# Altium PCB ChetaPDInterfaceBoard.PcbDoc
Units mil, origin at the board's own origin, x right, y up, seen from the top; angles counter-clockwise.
Board outline 6400 x 2000 mil, 2 copper layers (Top Layer, Bottom Layer); 32 components, 24 nets, 95 pads, 24 vias.
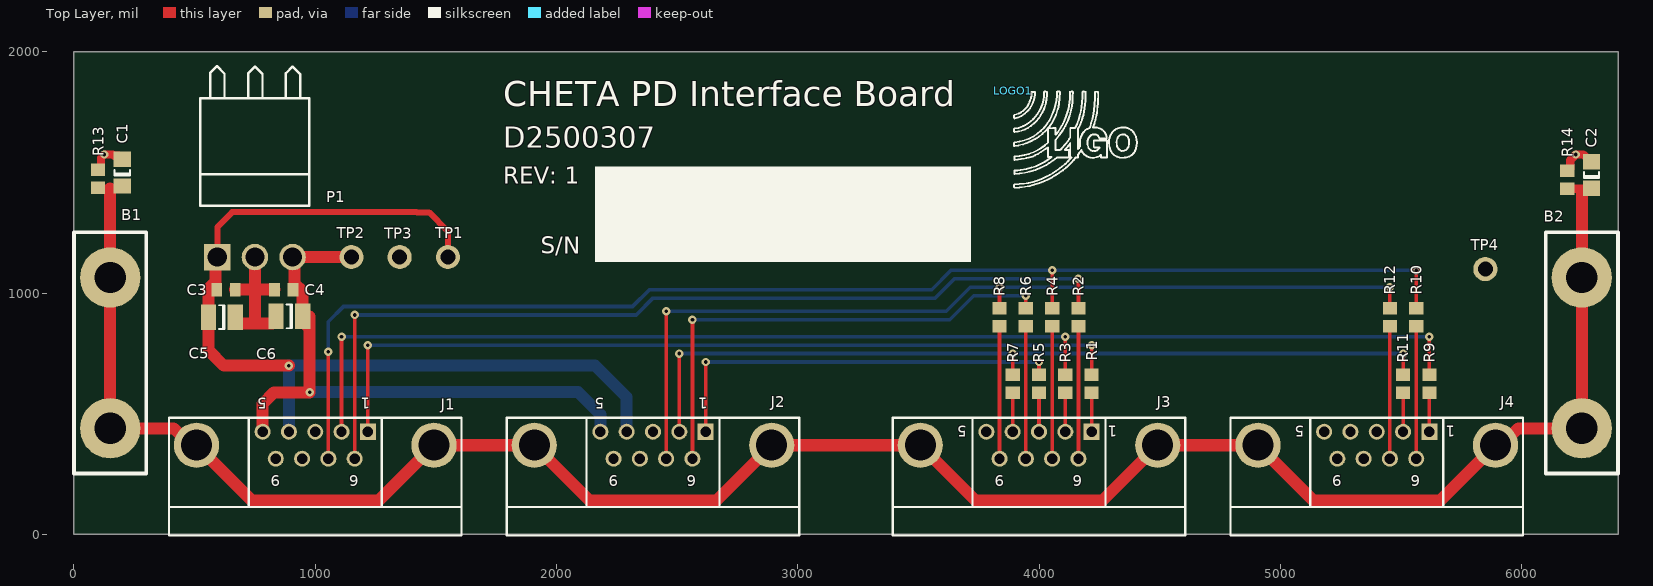
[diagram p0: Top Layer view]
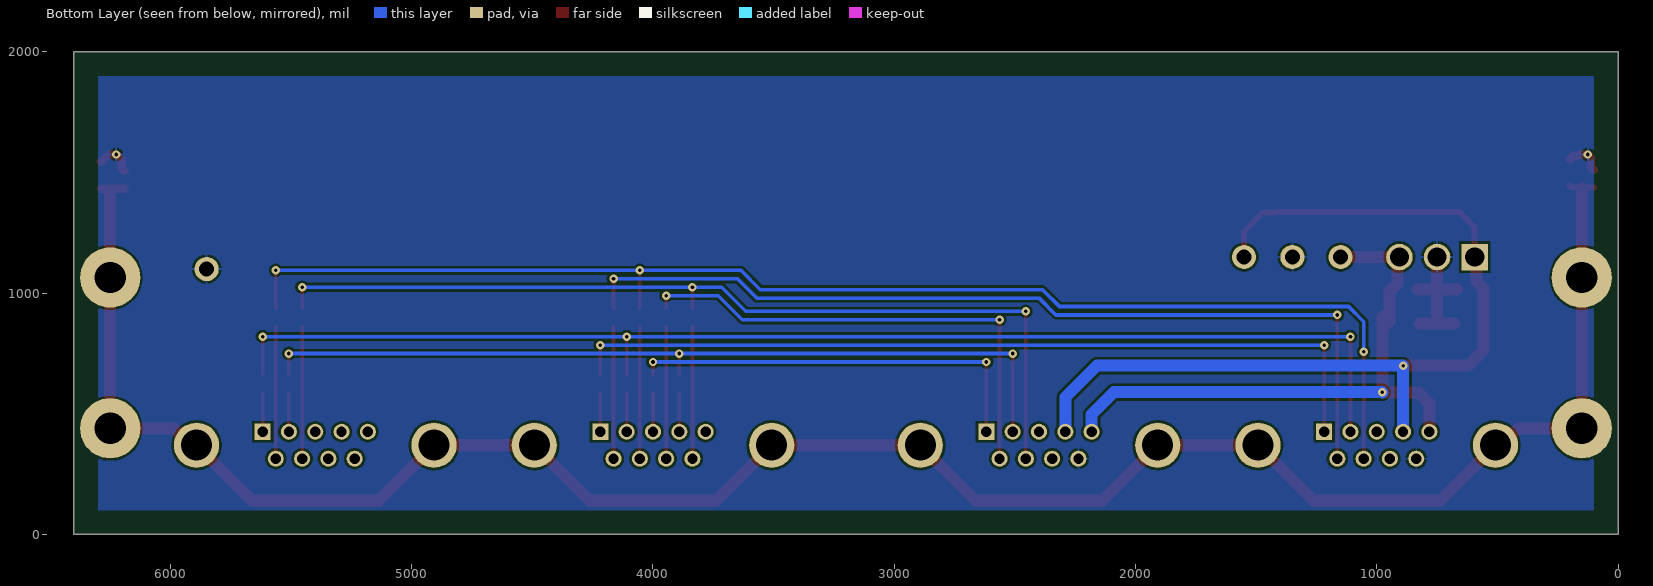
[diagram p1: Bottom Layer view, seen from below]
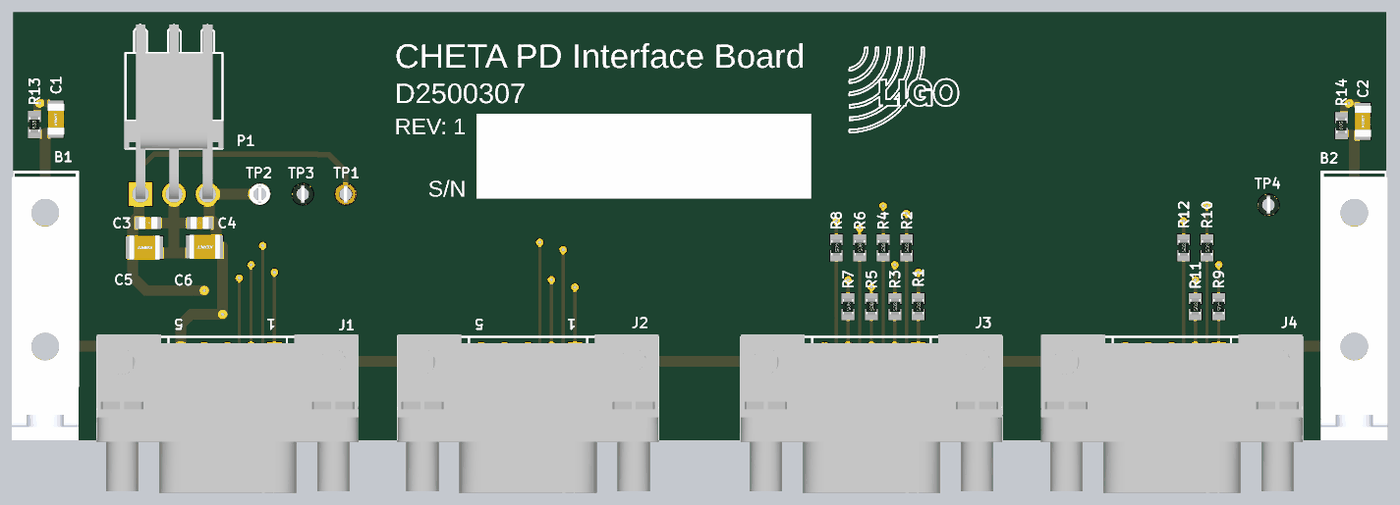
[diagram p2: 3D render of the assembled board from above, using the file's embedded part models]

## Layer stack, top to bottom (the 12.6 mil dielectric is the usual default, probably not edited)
Top Solder: solder mask 0.4, Solder Resist, Dk 3.5
Top Layer: signal copper 1.4
Dielectric 1: dielectric 12.6, FR-4, Dk 4.8
Bottom Layer: signal copper 1.4
Bottom Solder: solder mask 0.4, Solder Resist, Dk 3.5

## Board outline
0,0 0,2000 6400,2000 6400,0

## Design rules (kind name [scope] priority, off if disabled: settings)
Clearance [All] p1: gap=10 ignorepadtopadclearanceinfootprint=FALSE
HoleSize [All] p1: absolutevalues=TRUE maxlimit=200 minlimit=10 maxpercent=80.000 minpercent=20.000
MinimumAnnularRing [All] p1: minimumring=10
MinimumSolderMaskSliver [All] p1: minsoldermaskwidth=1
PolygonConnect [All] p1: connectstyle=Relief reliefconductorwidth=10 reliefentries=4 polygonreliefangle="90 Angle" airgapwidth=10
RoutingVias [All] p1: holewidth=15 width=35 viastyle="Through Hole" minholewidth=10 minwidth=25 maxholewidth=35 maxwidth=50
SilkToSolderMaskClearance [IsPad] p1: minsilkscreentomaskgap=7 clearancetoexposedcopper=TRUE
SolderMaskExpansion [All] p1: expansion=4 istentingtop=FALSE
SupplyNets "Schematic Supply Nets_2" [InNet('GND')] p1: voltage=0.000
SupplyNets "Schematic Supply Nets_1" [InNet('+15')] p2: voltage=0.000
SupplyNets "Schematic Supply Nets" [InNet('-15')] p3: voltage=0.000
Width [All] p1: maxlimit=100 minlimit=10 preferedwidth=15
27 further rules are at their usual default settings.

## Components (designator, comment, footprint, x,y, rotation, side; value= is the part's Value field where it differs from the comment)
B1 "Bracket" Bracket-RA_708 150,440 r0 top locked
B2 "Bracket" Bracket-RA_708 6250,440 r0 top locked
C1 "NL" CC3216-1206 200,1500 r90 top
C2 "NL" CC3216-1206 6290,1490 r90 top
C3 "100n" CC2013-0805 630,1015 r180 top
C4 "100n" CC2013-0805 870,1015 r180 top
C5 "10u" CC3225-1210 613,901 r180 top
C6 "10u" CC3225-1210 893,904 r180 top
J1 "DB9F" DB9F-RA 1000,370 r180 top locked
J2 "DB9F" DB9F-RA 2400,370 r180 top locked
J3 "DB9F" DB9F-RA 4000,370 r180 top locked
J4 "DB9F" DB9F-RA 5400,370 r180 top locked
LOGO1 "LIGO logo" LIGO_LOGO 3894,1839 r0 top
P1 "Header 3H" Molex_156_RA_3 594,1150 r90 top
R1 "10" CR2012-0805 4218.11,625 r270 top locked
R2 "10" CR2012-0805 4163.58,900 r270 top locked
R3 "10" CR2012-0805 4109.06,625 r270 top locked
R4 "10" CR2012-0805 4054.53,900 r270 top locked
R5 "10" CR2012-0805 4000,625 r270 top locked
R6 "10" CR2012-0805 3945.47,900 r270 top locked
R7 "10" CR2012-0805 3890.94,625 r270 top locked
R8 "10" CR2012-0805 3836.42,900 r270 top locked
R9 "10" CR2012-0805 5618.11,625 r270 top locked
R10 "10" CR2012-0805 5563.58,900 r270 top locked
R11 "10" CR2012-0805 5509.06,625 r270 top locked
R12 "10" CR2012-0805 5454.53,900 r270 top locked
R13 "NL" CR2012-0805 100,1475 r90 top
R14 "NL" CR2012-0805 6190,1470 r90 top
TP1 "+15" TP1-RED 1550,1150 r0 top
TP2 "-15" TP1-WHT 1150,1150 r0 top
TP3 "GND" TP1-BLK 1350,1150 r0 top
TP4 "GND" TP1-BLK 5850,1100 r0 top

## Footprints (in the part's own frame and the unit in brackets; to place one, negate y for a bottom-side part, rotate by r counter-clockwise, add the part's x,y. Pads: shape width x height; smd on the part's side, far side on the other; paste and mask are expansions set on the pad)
Bracket-RA_708 [mil] "Keystone Electronics right-angle 6-32 steel, 708"
  round 250 hole 130: 1(0,0) 2(0,625)
  silkscreen extent -150,-187 150,813, body extent -156,-439 156,791, height 390
CC2013-0805 [mm] "Chip Capacitor; Body 2.0 x 1.3 mm (LxW typ)"
  rect 1.15x1.4 smd: 1(-0.975,0) 2(0.975,0)
  body extent -1.1,-0.72 1.1,0.73, height 0.88
CC3216-1206 [mm] "Chip Capacitor; Body 3.2 x 1.6 mm (LxW typ)"
  rect 1.6x1.8 smd: 1(-1.4,0) 2(1.4,0)
  silkscreen extent -0.3,-0.8 0.3,0.8, body extent -1.85,-0.97 1.85,0.97, height 0.88
CC3225-1210 [mm] "Chip Capacitor; Body 3.2 x 2.5 mm (LxW typ)"
  rect 1.6x2.7 smd: 1(-1.4,0) 2(1.4,0)
  silkscreen extent -0.3,-1.25 0.3,1.25, body extent -1.85,-1.45 1.85,1.45, height 1.4
CR2012-0805 [mm] "Chip Resistor; Body 2.0 x 1.3 mm (LxW typ)"
  rect 1.3x1.5 smd: 1(-0.95,0) 2(0.95,0)
  body extent -1,-0.62 1,0.63, height 0.46
DB9F-RA [mm] "Receptiacle; D Subminiature 9 Position; Right Angle"
  rect 1.69x1.69 hole 1.09: 1(-5.54,-1.42)
  round 1.69 hole 1.09: 2(-2.77,-1.42) 3(0,-1.42) 4(2.77,-1.42) 5(5.54,-1.42) 6(-4.155,1.42) 7(-1.385,1.42) 8(1.385,1.42) 9(4.155,1.42)
  round 4.76 hole 3.26: 10(-12.495,0) 11(12.495,0)
  silkscreen extent -15.4,-2.9 15.4,9.5, body extent -15.49,-3.17 15.49,15.72, height 12.62
LIGO_LOGO [mil] "LIGO logo"
  silkscreen extent 3,-402 511,-3
Molex_156_RA_3 [mil]
  rect 110x110 hole 80: 1(0,0)
  round 110 hole 80: 2(0,-156) 3(0,-312)
  silkscreen extent 213,-382 792,70, body extent -24,-386 792,76, height 394
TP1-BLK [mm] "Testpoint pin, black"
  round 2.54 hole 1.58: 1(0,0)
  body extent -1.27,-1.27 1.27,1.27, height 4.89
TP1-RED [mm] "Testpoint pin, red"
  round 2.54 hole 1.58: 1(0,0)
  body extent -1.27,-1.27 1.27,1.27, height 4.89
TP1-WHT [mm] "Testpoint pin, white"
  round 2.54 hole 1.58: 1(0,0)
  body extent -1.27,-1.27 1.27,1.27, height 4.89

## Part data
B1 B2: library part Bracket_708, "Keystone Electronics right-angle 6-32 steel, 708", Part Number=36-708-ND
C1 C2: library part ChipCap, "Capacitor, surface mount", Tolerance=10%
C3 C4: library part ChipCap, "Capacitor, surface mount", Part Number=311-1140-1-ND, Tolerance=10%
C5 C6: library part ChipCap, "Capacitor, surface mount", Part Number=490-4798-1-ND, Tolerance=10%, Voltage Rating=50V
J1 J2 J3 J4: "Receptacle Assembly, 9 Position, Right Angle, .318 Series", Part Number=A32119-ND
LOGO1: library part LIGO_logo
P1: "Header, 3-Pin, Right Angle", Part Number=WM5236-ND
R1 R2 R3 R4 R5 R6 R7 R8 R9 R10 R11 R12: library part ChipRes1, "Resistor, surface mount", Part Number=RR12Q10DCT-ND, Tolerance=0.5%
R13 R14: library part ChipRes1, "Resistor, surface mount", Tolerance=0.5%
TP1: library part TP_POSITIVE, "Testpoint, red", Part Number=5005K-ND
TP2: library part TP_NEGATIVE, "Testpoint, white", Part Number=5007K-ND
TP3 TP4: library part TP_GND, "Testpoint, black", Part Number=5006K-ND

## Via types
v1: diameter 35, hole 15, Top Layer to Bottom Layer, 24 vias

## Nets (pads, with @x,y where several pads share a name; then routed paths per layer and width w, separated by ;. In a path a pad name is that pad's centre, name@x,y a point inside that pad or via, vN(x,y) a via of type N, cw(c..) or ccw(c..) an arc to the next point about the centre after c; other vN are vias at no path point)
+15: C3.2 C5.2 J1.4 J2.4 P1.1 TP1.1 | length 3877.8
  Top Layer w25: P1.1 594,1274 656,1336 1420,1336 1421,1335 1472,1335 1550,1257 TP1.1
  Top Layer w50: P1.1 587.29,1143.29 587.29,1049.29 558,1020 558,763 621,700 v1(890.94,700)
  Bottom Layer w50: J1.4 v1(890.94,700) 2160,700 2290.94,569.06 J2.4
-15: C4.1 C6.1 J1.5 J2.5 P1.3 TP2.1 | length 2507.9
  Top Layer w50: J1.5 781.89,541.89 829,589 v1(977,589) C6.1@977,903.46 ; P1.3 P1.3@908.39,1150 ; C6.1@948.12,882.35 C6.1@977,853.46 ; C6.1 947,905.12 947,1007 914.12,1039.88 914.12,1144.27 P1.3@908.39,1150 ; TP2.1 P1.3@908.39,1150
  Bottom Layer w50: v1(977,589) 978,590 2090,590 2181.89,498.11 J2.5
B1: B1.1 B1.2 B2.1 B2.2 C1.1 C2.1 J1.10 J1.11 J2.10 J2.11 J3.10 J3.11 J4.10 J4.11 R13.1 R14.1 | length 9095.6
  Top Layer w25: R13.1 146.36,1437.6 ; 150,1433.96 146.36,1437.6 ; C1.1 192.72,1437.6 146.36,1437.6 ; J1.11@483.24,370 J1.11 ; 6238.86,1432.6 6250,1421.46 ; C2.1@6287.72,1432.6 C2.1
  Top Layer w35: R14.1 6238.86,1432.6 C2.1@6287.72,1432.6
  Top Layer w50: 150,1433.96 B1.2 B1.1 413.24,440 J1.11@483.24,370 ; J1.11 738.07,140 1261.93,140 J1.10 J2.11 2138.07,140 2661.93,140 J2.10 J3.11 3738.07,140 4261.93,140 J3.10 J4.11 5138.07,140 5661.93,140 J4.10 ; J4.10@5916.76,370 5986.76,440 B2.1 B2.2 6250,1421.46
GND: C1.2 C2.2 C3.1 C4.2 C5.1 C6.2 J1.9 J2.9 P1.2 R13.2 R14.2 TP3.1 TP4.1 | length 903.8
  Top Layer w35: R13.2 103.94,1512.4 112.03,1520.49 112.03,1562.03 v1(125,1575) 161.56,1575 167.45,1569.11 186,1569.11 C1.2 ; R14.2 6193.94,1507.4 6202.03,1515.49 6202.03,1552.03 v1(6225,1575) 6256.18,1575 6286.06,1545.12 C2.2
  Top Layer w50: C3.1 750,1015 C4.2 ; C5.1@677.36,875 750,875 ; P1.2 750,1030 750,875 ; C6.2@822.64,875 750,875
NetJ3_1: J3.1 R1.2 | length 161.7
  Top Layer w15: J3.1 R1.2
NetJ3_2: J3.2 R3.2 | length 161.7
  Top Layer w15: J3.2 R3.2
NetJ3_3: J3.3 R5.2 | length 161.7
  Top Layer w15: J3.3 R5.2
NetJ3_4: J3.4 R7.2 | length 161.7
  Top Layer w15: J3.4 R7.2
NetJ3_6: J3.6 R2.2 | length 548.5
  Top Layer w15: J3.6 R2.2
NetJ3_7: J3.7 R4.2 | length 548.5
  Top Layer w15: J3.7 R4.2
NetJ3_8: J3.8 R6.2 | length 548.5
  Top Layer w15: J3.8 R6.2
NetJ3_9: J3.9 R8.2 | length 548.5
  Top Layer w15: J3.9 R8.2
NetJ4_1: J4.1 R9.2 | length 161.7
  Top Layer w15: J4.1 R9.2
NetJ4_2: J4.2 R11.2 | length 161.7
  Top Layer w15: J4.2 R11.2
NetJ4_6: J4.6 R10.2 | length 548.5
  Top Layer w15: J4.6 R10.2
NetJ4_7: J4.7 R12.2 | length 548.5
  Top Layer w15: J4.7 R12.2
PD1_AC_N: J1.6 R2.1 | length 3779.7
  Top Layer w15: J1.6 v1(1163.58,910) ; R2.1 v1(4163.58,1060)
  Bottom Layer w15: v1(1163.58,910) 2329.05,910 ; 2330,910 2400,980 3569.5,980 3649.5,1060 v1(4163.58,1060)
PD1_AC_P: J1.1 R1.1 | length 3482.5
  Top Layer w15: J1.1 v1(1218.11,785) ; R1.1 v1(4218.11,785)
  Bottom Layer w15: v1@1217.31,785 v1(4218.11,785)
PD1_DC_N: J1.7 R4.1 R10.1 | length 5481.1
  Top Layer w15: v1(1054,758) 1054,314.62 J1.7 ; R4.1 v1(4054.53,1095) ; R10.1 v1(5563.58,1095)
  Bottom Layer w15: v1(1054,758) 1054,882 1117,945 2315.19,945 2385.19,1015 3555,1015 3635,1095 v1(4054.53,1095) v1(5563.58,1095)
PD1_DC_P: J1.2 R3.1 R9.1 | length 5218.3
  Top Layer w15: J1.2 v1(1109.05,820) ; R3.1 v1(4109.06,820) ; R9.1 v1(5618.11,820)
  Bottom Layer w15: v1(1109.05,820) v1(4109.06,820) v1(5618.11,820)
PD2_AC_N: J2.6 R6.1 | length 2051.8
  Top Layer w15: J2.6 v1(2563.58,890) ; R6.1 v1(3945.47,990)
  Bottom Layer w15: v1(2563.58,890) 3630,890 3730,990 v1(3945.47,990)
PD2_AC_P: J2.1 R5.1 | length 1723.6
  Top Layer w15: J2.1 v1(2618.11,715) ; R5.1 v1(4000,715)
  Bottom Layer w15: v1(2618.11,715) v1(4000,715)
PD2_DC_N: J2.7 R8.1 R12.1 | length 3827.5
  Top Layer w15: J2.7 v1(2454.53,925) ; R8.1 v1(3836.42,1025) ; R12.1 v1(5454.53,1025)
  Bottom Layer w15: v1(2454.53,925) 3615.5,925 3715.5,1025 v1(3836.42,1025) v1(5454.53,1025)
PD2_DC_P: J2.2 R7.1 R11.1 | length 3499.3
  Top Layer w15: J2.2 v1(2509.06,750) ; R7.1 v1(3890.94,750) ; R11.1 v1(5509.06,750)
  Bottom Layer w15: v1(2509.06,750) v1(3890.94,750) v1(5509.06,750)
pads on no net: J1.3 J1.8 J2.3 J2.8 J3.5 J4.3 J4.4 J4.5 J4.8 J4.9

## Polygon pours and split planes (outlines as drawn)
GND on Bottom Layer "GND_L02_P000" (solid, pour order 0): 100,1900 100,100 6300,100 6300,1900

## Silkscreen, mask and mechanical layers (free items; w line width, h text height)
Top Overlay:
  rectangle: 2159,1130 3719,1525
  text "CHETA PD Interface Board" at 1779,1740 h180
  text "D2500307" at 1779,1575 h150
  text "REV: 1" at 1779,1430 h120
  text "S/N" at 1934,1139 h120
Mechanical 1:
  the board outline again, w10
Drill Drawing:
  circle w10: c100.62,2435.83 r33.33
  lines w10: 67.29,2569.17 83.96,2569.17 83.96,2552.5 117.29,2552.5 117.29,2569.17 133.96,2569.17 133.96,2602.5 117.29,2602.5 117.29,2619.17 83.96,2619.17 83.96,2602.5 67.29,2602.5 67.29,2569.17 ; 67.29,2702.5 133.96,2702.5 133.96,2769.17 67.29,2769.17 67.29,2702.5 ; 67.29,2919.17 133.96,2919.17 100.62,2852.5 67.29,2919.17 ; 67.29,3019.17 83.96,3019.17 100.62,3002.5 117.29,3019.17 133.96,3019.17 117.29,3035.83 133.96,3052.5 117.29,3052.5 100.62,3069.17 83.96,3052.5 67.29,3052.5 83.96,3035.83 67.29,3019.17 ; 67.29,3152.5 100.62,3169.17 133.96,3152.5 117.29,3185.83 133.96,3219.17 100.62,3202.5 67.29,3219.17 83.96,3185.83 67.29,3152.5
  lines w15: 7.5,2357.5 10538.58,2357.5 ; 7.5,3257.5 10538.58,3257.5 ; 558.38,2207.5 558.38,3407.5 ; 1098.24,2207.5 1098.24,3407.5 ; 2247.9,2207.5 2247.9,3407.5 ; 2753.78,2207.5 2753.78,3407.5 ; 3487.58,2207.5 3487.58,3407.5 ; 4987.13,2207.5 4987.13,3407.5 ; 5576.98,2207.5 5576.98,3407.5 ; 6322.78,2207.5 6322.78,3407.5 ; 6972.6,2207.5 6972.6,3407.5 ; 7826.37,2207.5 7826.37,3407.5 ; 9159.98,2207.5 9159.98,3407.5 ; 7.5,2207.5 10538.58,2207.5 10538.58,3407.5 7.5,3407.5 7.5,2207.5
  text "Symbol" at 97.5,3302.5 h72
  text "Count" at 603.38,3302.5 h72
  text "Hole Size" at 1143.24,3302.5 h72
  text "Plated" at 2292.9,3302.5 h72
  text "Hole Type" at 2798.78,3302.5 h72
  text "Drill Layer Pair" at 3532.58,3302.5 h72
  text "Via/Pad" at 5032.13,3302.5 h72
  text "Pad Shape" at 5621.98,3302.5 h72
  text "Template" at 6367.78,3302.5 h72
  text "Description" at 7017.6,3302.5 h72
  text "Hole Tolerance (+)" at 7871.37,3302.5 h72
  text "Hole Tolerance (-)" at 9204.98,3302.5 h72
  text "3" at 603.38,3152.5 h60
  text "80.00mil (2.032mm)" at 1143.24,3152.5 h60
  text "PTH" at 2292.9,3152.5 h60
  text "Round" at 2798.78,3152.5 h60
  text "Top Layer - Bottom Layer" at 3532.58,3152.5 h60
  text "Pad" at 5032.13,3152.5 h60
  text "(Mixed)" at 5621.98,3152.5 h60
  text "(Mixed)" at 6367.78,3152.5 h60
  text "4" at 603.38,3002.5 h60
  text "62.21mil (1.580mm)" at 1143.24,3002.5 h60
  text "PTH" at 2292.9,3002.5 h60
  text "Round" at 2798.78,3002.5 h60
  text "Top Layer - Bottom Layer" at 3532.58,3002.5 h60
  text "Pad" at 5032.13,3002.5 h60
  text "Rounded" at 5621.98,3002.5 h60
  text "c254h158" at 6367.78,3002.5 h60
  text "4" at 603.38,2852.5 h60
  text "130.00mil (3.302mm)" at 1143.24,2852.5 h60
  text "PTH" at 2292.9,2852.5 h60
  text "Round" at 2798.78,2852.5 h60
  text "Top Layer - Bottom Layer" at 3532.58,2852.5 h60
  text "Pad" at 5032.13,2852.5 h60
  text "Rounded" at 5621.98,2852.5 h60
  text "c635h330" at 6367.78,2852.5 h60
  text "8" at 603.38,2702.5 h60
  text "128.35mil (3.260mm)" at 1143.24,2702.5 h60
  text "PTH" at 2292.9,2702.5 h60
  text "Round" at 2798.78,2702.5 h60
  text "Top Layer - Bottom Layer" at 3532.58,2702.5 h60
  text "Pad" at 5032.13,2702.5 h60
  text "Rounded" at 5621.98,2702.5 h60
  text "c476h326" at 6367.78,2702.5 h60
  text "24" at 603.38,2552.5 h60
  text "15.00mil (0.381mm)" at 1143.24,2552.5 h60
  text "PTH" at 2292.9,2552.5 h60
  text "Round" at 2798.78,2552.5 h60
  text "Top Layer - Bottom Layer" at 3532.58,2552.5 h60
  text "Via" at 5032.13,2552.5 h60
  text "Rounded" at 5621.98,2552.5 h60
  text "v89h38" at 6367.78,2552.5 h60
  text "36" at 603.38,2402.5 h60
  text "42.91mil (1.090mm)" at 1143.24,2402.5 h60
  text "PTH" at 2292.9,2402.5 h60
  text "Round" at 2798.78,2402.5 h60
  text "Top Layer - Bottom Layer" at 3532.58,2402.5 h60
  text "Pad" at 5032.13,2402.5 h60
  text "(Mixed)" at 5621.98,2402.5 h60
  text "(Mixed)" at 6367.78,2402.5 h60
  text "79 Total" at 603.38,2252.5 h60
